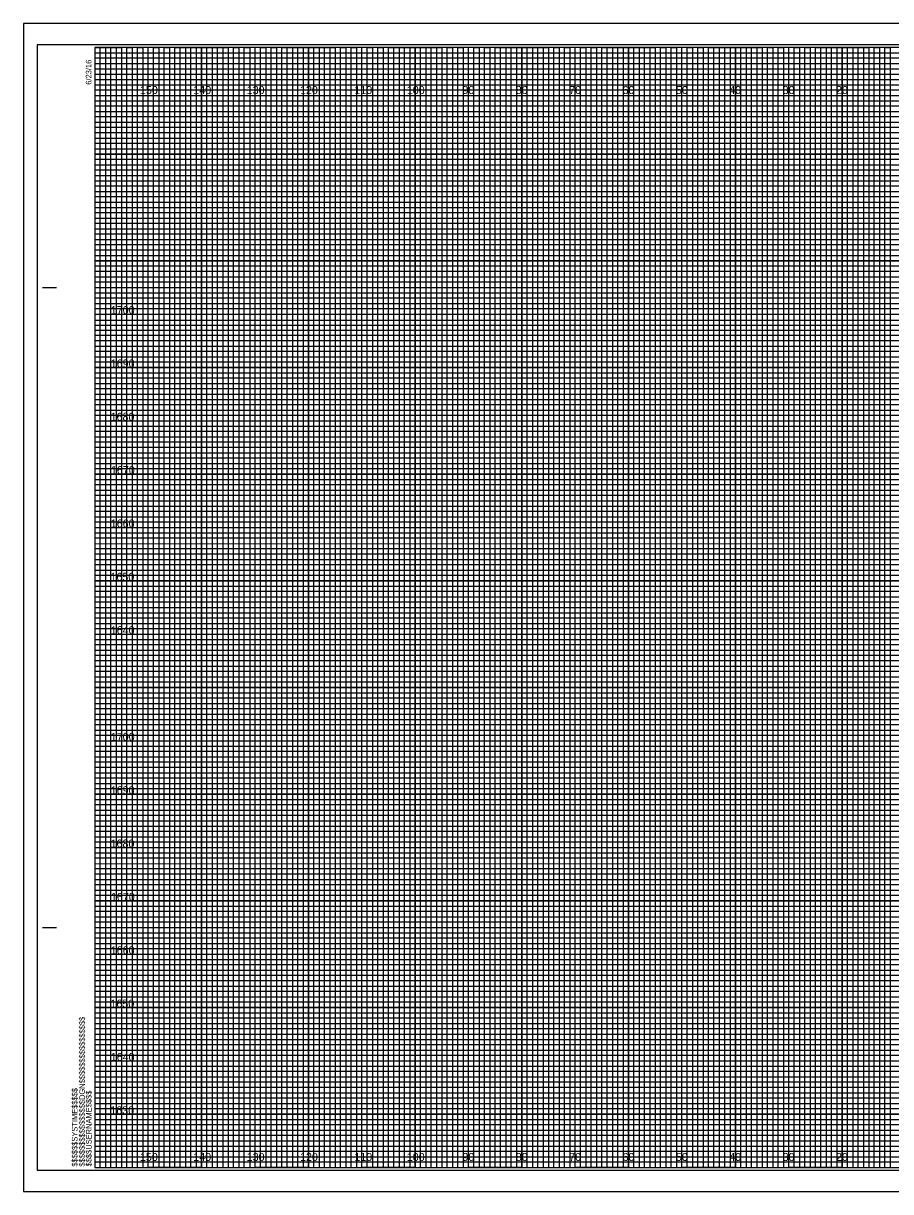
# Model space of a CAD drawing. Extents: x -419 to 4739, y -630 to 13534.
# Drawn here: x 2287.9 to 2450.4, y 635 to 854 of the extents above; entities that cross this region are included whole.
import ezdxf

# ---------------------------------------------------------------- set-up
doc = ezdxf.new("R2010")
doc.units = 0
for name, color, linetype in [('Old_Level_62', 7, 'Continuous'), ('Pattern 1', 7, 'Continuous'), ('Pattern 18', 7, 'Continuous'), ('Pattern 4', 7, 'Continuous'), ('Pattern 5', 7, 'Continuous'), ('Prop Dimension', 7, 'Continuous'), ('Prop Horizontal Alignment', 7, 'Continuous'), ('Raster_Level_0', 7, 'Continuous'), ('Scratch_Level_0', 7, 'Continuous'), ('Scratch_Level_3', 7, 'Continuous'), ('Scratch_Level_5', 7, 'Continuous')]:
    doc.layers.add(name, color=color, linetype=linetype)

msp = doc.modelspace()

# ---------------------------------------------------------------- linework, layer by layer
at = {"layer": 'Old_Level_62'}
for p, q in [((2291.53, 804.53), (2294.03, 804.53)), ((2291.63, 804.53), (2294.13, 804.53)), ((2291.53, 684.53), (2294.03, 684.53)), ((2291.63, 684.53), (2294.13, 684.53)), ((2301.33, 639.53), (2301.33, 639.53)), ((2301.33, 639.53), (2301.33, 639.53)), ((2301.33, 639.53), (2301.33, 639.53)), ((2301.33, 639.53), (2301.33, 639.53)), ((2301.33, 639.53), (2301.33, 639.53)), ((2301.33, 639.53), (2301.33, 639.53)), ((2301.33, 639.53), (2301.33, 639.53))]:
    msp.add_line(p, q, dxfattribs=at)
msp.add_lwpolyline([(2621.33, 849.53), (2301.33, 849.53), (2301.33, 639.53), (2621.33, 639.53)], close=True, dxfattribs=at)
at = {"layer": 'Pattern 18'}
msp.add_lwpolyline([(2287.93, 635.03), (2624.63, 635.03), (2624.63, 854.03), (2287.93, 854.03)], close=True, dxfattribs=at)
at = {"layer": 'Pattern 4'}
for p, q in [((2301.33, 848.53), (2561.33, 848.53)), ((2561.33, 847.51), (2301.33, 847.51)), ((2301.33, 847.51), (2301.33, 846.53)), ((2301.33, 846.53), (2561.33, 846.53)), ((2561.33, 845.42), (2301.33, 845.42)), ((2301.33, 845.42), (2301.33, 843.53)), ((2301.33, 843.53), (2621.33, 843.53))]:
    msp.add_line(p, q, dxfattribs=at)
for points in [[(2301.33, 842.53), (2571.33, 842.53), (2621.33, 842.53), (2621.33, 841.53), (2301.33, 841.53)], [(2301.33, 840.53), (2621.33, 840.53), (2621.33, 838.53), (2301.33, 838.53)], [(2301.33, 837.53), (2621.33, 837.53), (2621.33, 836.53), (2301.33, 836.51)], [(2301.33, 835.53), (2621.33, 835.53), (2621.33, 833.53), (2301.33, 833.53)], [(2301.33, 832.53), (2621.33, 832.53), (2621.33, 831.53), (2301.33, 831.53)], [(2301.33, 830.53), (2621.33, 830.53), (2621.33, 828.53), (2301.33, 828.53)], [(2301.33, 827.53), (2621.33, 827.53), (2621.33, 826.53), (2301.33, 826.53)], [(2301.33, 825.53), (2621.33, 825.53), (2621.33, 823.53), (2301.33, 823.53)], [(2301.33, 822.53), (2621.33, 822.53), (2621.33, 821.53), (2301.33, 821.53)], [(2301.33, 820.53), (2621.33, 820.53), (2621.33, 818.53), (2301.33, 818.53)], [(2301.33, 817.53), (2621.33, 817.53), (2621.33, 816.53), (2301.33, 816.53)], [(2301.33, 815.53), (2621.33, 815.53), (2621.33, 813.48), (2621.33, 812.53), (2621.33, 811.53), (2301.33, 811.53)], [(2301.33, 813.53), (2621.33, 813.53), (2621.33, 812.53), (2301.33, 812.53)], [(2301.33, 810.53), (2621.33, 810.53), (2621.33, 808.53), (2301.33, 808.56)], [(2301.33, 808.56), (2621.33, 808.53), (2621.33, 807.53), (2301.33, 807.53)], [(2301.33, 806.53), (2621.33, 806.53), (2621.33, 805.53), (2301.33, 805.53)], [(2301.33, 803.53), (2621.33, 803.53), (2621.33, 802.53), (2301.33, 802.53)], [(2301.33, 801.53), (2621.33, 801.53), (2621.33, 800.53), (2301.33, 800.53)], [(2301.26, 798.42), (2621.33, 798.42), (2621.33, 797.41), (2301.26, 797.41)], [(2301.33, 796.53), (2621.33, 796.53), (2621.33, 795.53), (2301.33, 795.53)], [(2301.33, 793.53), (2621.33, 793.53), (2621.33, 792.53), (2301.33, 792.53)], [(2301.33, 791.53), (2621.33, 791.53), (2621.33, 790.53), (2301.33, 790.53)], [(2301.33, 788.53), (2621.33, 788.53), (2621.33, 787.53), (2301.33, 787.53)], [(2301.33, 786.53), (2621.33, 786.53), (2621.33, 785.53), (2301.33, 785.53)], [(2301.33, 783.53), (2621.33, 783.53), (2621.33, 782.53), (2301.33, 782.53)], [(2301.33, 781.53), (2621.33, 781.53), (2621.33, 780.53), (2301.33, 780.53)], [(2301.33, 778.53), (2621.33, 778.53), (2621.32, 777.51), (2301.33, 777.53)], [(2301.33, 776.53), (2621.33, 776.53), (2621.33, 775.53), (2301.33, 775.53)], [(2301.33, 773.53), (2621.33, 773.53), (2621.33, 772.53), (2301.33, 772.53)], [(2301.33, 771.53), (2621.33, 771.53), (2621.33, 770.53), (2301.33, 770.53)], [(2301.33, 768.53), (2621.33, 768.53), (2621.33, 767.53), (2301.33, 767.53)], [(2301.33, 766.53), (2621.33, 766.53), (2621.33, 765.53), (2301.33, 765.53)], [(2301.33, 763.53), (2621.33, 763.53), (2621.33, 762.53), (2301.33, 762.53)], [(2301.33, 761.53), (2621.33, 761.53), (2621.33, 760.53), (2301.33, 760.53)], [(2301.33, 758.53), (2621.33, 758.53), (2621.33, 757.53), (2301.33, 757.53)], [(2301.33, 756.52), (2621.4, 756.44), (2621.33, 755.53), (2301.33, 755.53)], [(2301.33, 753.53), (2621.33, 753.53), (2621.33, 752.53), (2301.33, 752.53)], [(2301.33, 751.53), (2621.33, 751.53), (2621.33, 750.53), (2301.33, 750.53)], [(2301.33, 748.53), (2621.33, 748.53), (2621.33, 747.53), (2301.33, 747.53)], [(2301.33, 746.53), (2621.33, 746.53), (2621.33, 745.53), (2301.33, 745.53)], [(2301.33, 743.53), (2621.33, 743.53), (2621.33, 742.53), (2301.33, 742.53)], [(2301.33, 741.53), (2621.33, 741.53), (2621.33, 740.53), (2301.33, 740.53)], [(2301.33, 738.53), (2621.33, 738.53), (2621.33, 737.53), (2301.33, 737.53)], [(2301.33, 736.53), (2621.33, 736.53), (2621.33, 735.53), (2301.33, 735.53)], [(2301.33, 733.53), (2621.33, 733.53), (2621.33, 732.53), (2301.33, 732.53)], [(2301.33, 731.53), (2621.33, 731.53), (2621.33, 730.53), (2301.33, 730.53)], [(2301.33, 728.53), (2621.33, 728.53), (2621.33, 727.53), (2301.33, 727.53)], [(2301.33, 726.53), (2621.33, 726.53), (2621.33, 725.53), (2301.33, 725.53)], [(2301.33, 723.53), (2621.33, 723.53), (2621.33, 722.53), (2301.33, 722.53)], [(2301.33, 721.53), (2621.33, 721.53), (2621.33, 720.53), (2301.33, 720.53)], [(2301.33, 718.53), (2621.33, 718.53), (2621.32, 717.51), (2301.33, 717.53)], [(2301.33, 716.53), (2621.33, 716.53), (2621.33, 715.53), (2301.33, 715.53)], [(2301.33, 713.53), (2621.33, 713.53), (2621.33, 712.53), (2301.33, 712.53)], [(2301.33, 711.53), (2621.33, 711.53), (2621.33, 710.53), (2301.33, 710.53)], [(2301.33, 708.53), (2621.33, 708.53), (2621.33, 707.53), (2301.33, 707.53)], [(2301.33, 706.53), (2621.33, 706.53), (2621.33, 705.53), (2301.33, 705.53)], [(2301.33, 703.53), (2621.33, 703.53), (2621.33, 702.53), (2301.33, 702.53)], [(2301.33, 701.53), (2621.33, 701.53), (2621.33, 700.53), (2301.33, 700.53)], [(2301.33, 698.53), (2621.33, 698.53), (2621.33, 697.53), (2301.33, 697.53)], [(2301.33, 696.52), (2621.4, 696.44), (2621.33, 695.53), (2301.33, 695.53)], [(2301.33, 693.53), (2621.33, 693.53), (2621.33, 692.53), (2301.33, 692.53)], [(2301.33, 691.53), (2621.33, 691.53), (2621.33, 690.53), (2301.33, 690.53)], [(2301.33, 688.53), (2621.33, 688.53), (2621.33, 687.53), (2301.33, 687.53)], [(2301.33, 686.53), (2621.33, 686.53), (2621.33, 685.53), (2301.33, 685.53)], [(2301.33, 683.53), (2621.33, 683.53), (2621.33, 682.53), (2301.33, 682.53)], [(2301.33, 681.53), (2621.33, 681.53), (2621.33, 680.53), (2301.33, 680.53)], [(2301.33, 678.53), (2621.33, 678.53), (2621.33, 677.53), (2301.33, 677.53)], [(2301.33, 676.53), (2621.33, 676.53), (2621.33, 675.53), (2301.33, 675.53)], [(2301.33, 673.53), (2621.33, 673.53), (2621.33, 672.53), (2301.33, 672.53)], [(2301.33, 671.53), (2621.33, 671.53), (2621.33, 670.53), (2301.33, 670.53)], [(2301.33, 668.53), (2621.33, 668.53), (2621.33, 667.53), (2301.33, 667.53)], [(2301.33, 666.53), (2621.33, 666.53), (2621.33, 665.53), (2301.33, 665.53)], [(2301.33, 663.53), (2621.33, 663.53), (2621.33, 662.53), (2301.33, 662.53)], [(2301.33, 661.53), (2621.33, 661.53), (2621.33, 660.53), (2301.33, 660.53)], [(2301.33, 658.53), (2621.33, 658.53), (2621.33, 657.53), (2301.33, 657.53)], [(2301.33, 656.53), (2621.33, 656.53), (2621.33, 655.53), (2301.33, 655.53)], [(2301.33, 653.53), (2621.33, 653.53), (2621.33, 652.53), (2301.33, 652.53)], [(2301.33, 651.53), (2621.33, 651.53), (2621.33, 650.53), (2301.33, 650.53)], [(2301.33, 648.53), (2621.33, 648.53), (2621.33, 647.53), (2301.33, 647.53)], [(2301.33, 646.53), (2621.33, 646.53), (2621.33, 645.53), (2301.33, 645.53)], [(2301.33, 643.53), (2621.33, 643.53), (2621.33, 642.53), (2301.33, 642.53)], [(2301.33, 641.53), (2621.33, 641.53), (2621.33, 640.53), (2301.33, 640.53)]]:
    msp.add_lwpolyline(points, dxfattribs=at)
at = {"layer": 'Pattern 5'}
for p, q in [((2624.63, 854.03), (2287.93, 854.03)), ((2287.93, 854.03), (2287.93, 635.03)), ((2287.93, 635.03), (2624.63, 635.03))]:
    msp.add_line(p, q, dxfattribs=at)
at = {"layer": 'Prop Dimension'}
for points in [[(2301.33, 639.53), (2302.33, 639.53), (2302.33, 849.53), (2303.33, 849.53), (2303.33, 639.53)], [(2303.33, 639.53), (2304.33, 639.53), (2304.33, 849.53), (2305.33, 849.53), (2305.33, 639.53)], [(2306.33, 639.53), (2307.33, 639.53), (2307.33, 849.53), (2308.33, 849.53), (2308.33, 639.53)], [(2308.33, 639.53), (2309.33, 639.53), (2309.33, 849.53), (2310.33, 849.53), (2310.33, 639.53)], [(2311.33, 639.53), (2312.33, 639.53), (2312.33, 849.53), (2313.33, 849.53), (2313.33, 639.53)], [(2313.33, 639.53), (2314.33, 639.53), (2314.33, 849.53), (2315.33, 849.53), (2315.33, 639.53)], [(2316.33, 639.53), (2317.33, 639.53), (2317.33, 849.53), (2318.33, 849.53), (2318.33, 639.53)], [(2318.33, 639.53), (2319.33, 639.53), (2319.33, 849.53), (2320.33, 849.53), (2320.33, 639.53)], [(2321.33, 639.53), (2322.33, 639.53), (2322.33, 849.53), (2323.33, 849.53), (2323.33, 639.53)], [(2323.33, 639.53), (2324.33, 639.53), (2324.33, 849.53), (2325.33, 849.53), (2325.33, 639.53)], [(2326.33, 639.53), (2327.33, 639.53), (2327.33, 849.53), (2328.33, 849.53), (2328.33, 639.53)], [(2328.33, 639.53), (2329.33, 639.53), (2329.33, 849.53), (2330.33, 849.53), (2330.33, 639.53)], [(2331.33, 639.53), (2332.33, 639.53), (2332.33, 849.53), (2333.33, 849.53), (2333.33, 639.53)], [(2333.33, 639.53), (2334.33, 639.53), (2334.33, 849.53), (2335.33, 849.53), (2335.33, 639.53)], [(2336.33, 639.53), (2337.33, 639.53), (2337.33, 849.53), (2338.33, 849.53), (2338.33, 639.53)], [(2338.33, 639.53), (2339.33, 639.53), (2339.33, 849.53), (2340.33, 849.53), (2340.33, 639.53)], [(2341.33, 639.53), (2342.33, 639.53), (2342.33, 849.53), (2343.33, 849.53), (2343.33, 639.53)], [(2343.33, 639.53), (2344.33, 639.53), (2344.33, 849.53), (2345.33, 849.53), (2345.33, 639.53)], [(2346.33, 639.53), (2347.33, 639.53), (2347.33, 849.53), (2348.33, 849.53), (2348.33, 639.53)], [(2348.33, 639.53), (2349.33, 639.53), (2349.33, 849.53), (2350.33, 849.53), (2350.33, 639.53)], [(2351.33, 639.53), (2352.33, 639.53), (2352.33, 849.53), (2353.33, 849.53), (2353.33, 639.53)], [(2353.33, 639.53), (2354.33, 639.53), (2354.33, 849.53), (2355.33, 849.53), (2355.33, 639.53)], [(2356.33, 639.53), (2357.33, 639.53), (2357.33, 849.53), (2358.33, 849.53), (2358.33, 639.53)], [(2358.33, 639.53), (2359.33, 639.53), (2359.33, 849.53), (2360.33, 849.53), (2360.33, 639.53)], [(2361.33, 639.53), (2362.33, 639.53), (2362.33, 849.53), (2363.33, 849.53), (2363.33, 639.53)], [(2363.33, 639.53), (2364.33, 639.53), (2364.33, 849.53), (2365.33, 849.53), (2365.33, 639.53)], [(2366.33, 639.53), (2367.33, 639.53), (2367.33, 849.53), (2368.33, 849.53), (2368.33, 639.53)], [(2368.33, 639.53), (2369.33, 639.53), (2369.33, 849.53), (2370.33, 849.53), (2370.33, 639.53)], [(2371.33, 639.53), (2372.33, 639.53), (2372.33, 849.53), (2373.33, 849.53), (2373.33, 639.53)], [(2373.33, 639.53), (2374.33, 639.53), (2374.33, 849.53), (2375.33, 849.53), (2375.33, 639.53)], [(2376.33, 639.53), (2377.33, 639.53), (2377.33, 849.53), (2378.33, 849.53), (2378.33, 639.53)], [(2378.33, 639.53), (2379.33, 639.53), (2379.33, 849.53), (2380.33, 849.53), (2380.33, 639.53)], [(2381.33, 639.53), (2382.33, 639.53), (2382.33, 849.53), (2383.33, 849.53), (2383.33, 639.53)], [(2383.33, 639.53), (2384.33, 639.53), (2384.33, 849.53), (2385.33, 849.53), (2385.33, 639.53)], [(2386.33, 639.53), (2387.33, 639.53), (2387.33, 849.53), (2388.33, 849.53), (2388.33, 639.53)], [(2388.33, 639.53), (2389.33, 639.53), (2389.33, 849.53), (2390.33, 849.53), (2390.33, 639.53)], [(2391.33, 639.53), (2392.33, 639.53), (2392.33, 849.53), (2393.33, 849.53), (2393.33, 639.53)], [(2393.33, 639.53), (2394.33, 639.53), (2394.33, 849.53), (2395.33, 849.53), (2395.33, 639.53)], [(2396.33, 639.53), (2397.33, 639.53), (2397.33, 849.53), (2398.33, 849.53), (2398.33, 639.53)], [(2398.33, 639.53), (2399.33, 639.53), (2399.33, 849.53), (2400.33, 849.53), (2400.33, 639.53)], [(2401.33, 639.53), (2402.33, 639.53), (2402.33, 849.53), (2403.33, 849.53), (2403.33, 639.53)], [(2403.33, 639.53), (2404.33, 639.53), (2404.33, 849.53), (2405.33, 849.53), (2405.33, 639.53)], [(2406.33, 639.53), (2407.33, 639.53), (2407.33, 849.53), (2408.33, 849.53), (2408.33, 639.53)], [(2408.33, 639.53), (2409.33, 639.53), (2409.33, 849.53), (2410.33, 849.53), (2410.33, 639.53)], [(2411.33, 639.53), (2412.33, 639.53), (2412.33, 849.53), (2413.33, 849.53), (2413.33, 639.53)], [(2413.33, 639.53), (2414.33, 639.53), (2414.33, 849.53), (2415.33, 849.53), (2415.33, 639.53)], [(2416.33, 639.53), (2417.33, 639.53), (2417.33, 849.53), (2418.33, 849.53), (2418.33, 639.53)], [(2418.33, 639.53), (2419.33, 639.53), (2419.33, 849.53), (2420.33, 849.53), (2420.33, 639.53)], [(2421.33, 639.53), (2422.33, 639.53), (2422.33, 849.53), (2423.33, 849.53), (2423.33, 639.53)], [(2423.33, 639.53), (2424.33, 639.53), (2424.33, 849.53), (2425.33, 849.53), (2425.33, 639.53)], [(2426.33, 639.53), (2427.33, 639.53), (2427.33, 849.53), (2428.33, 849.53), (2428.33, 639.53)], [(2428.33, 639.53), (2429.33, 639.53), (2429.33, 849.53), (2430.33, 849.53), (2430.33, 639.53)], [(2431.33, 639.53), (2432.33, 639.53), (2432.33, 849.53), (2433.33, 849.53), (2433.33, 639.53)], [(2433.33, 639.53), (2434.33, 639.53), (2434.33, 849.53), (2435.33, 849.53), (2435.33, 639.53)], [(2436.33, 639.53), (2437.33, 639.53), (2437.33, 849.53), (2438.33, 849.53), (2438.33, 639.53)], [(2438.33, 639.53), (2439.33, 639.53), (2439.33, 849.53), (2440.33, 849.53), (2440.33, 639.53)], [(2441.33, 639.53), (2442.33, 639.53), (2442.33, 849.53), (2443.33, 849.53), (2443.33, 639.53)], [(2443.33, 639.53), (2444.33, 639.53), (2444.33, 849.53), (2445.33, 849.53), (2445.33, 639.53)], [(2446.33, 639.53), (2447.33, 639.53), (2447.33, 849.53), (2448.33, 849.53), (2448.33, 639.53)], [(2448.33, 639.53), (2449.33, 639.53), (2449.33, 849.53), (2450.33, 849.53), (2450.33, 639.53)]]:
    msp.add_lwpolyline(points, dxfattribs=at)
at = {"layer": 'Prop Horizontal Alignment'}
for points in [[(2301.33, 849.53), (2306.33, 849.53), (2306.33, 639.53), (2316.33, 639.53), (2316.33, 849.53), (2326.33, 849.53), (2326.33, 639.53), (2336.33, 639.53), (2336.33, 849.53), (2346.33, 849.53), (2346.33, 639.53), (2356.33, 639.53), (2356.33, 849.53), (2366.33, 849.53), (2366.33, 639.53), (2376.33, 639.53), (2376.33, 849.53), (2386.33, 849.53), (2386.33, 639.53), (2396.33, 639.53), (2396.33, 849.53), (2406.33, 849.53), (2406.33, 639.53), (2416.33, 639.53), (2416.33, 849.53), (2426.33, 849.53), (2426.33, 639.53), (2436.33, 639.53), (2436.33, 849.53), (2446.33, 849.53), (2446.33, 639.53), (2456.33, 639.53)], [(2301.33, 844.53), (2576.33, 844.53)], [(2301.33, 824.53), (2621.33, 824.53), (2621.33, 834.53), (2301.33, 834.53)], [(2301.33, 804.53), (2621.33, 804.53), (2621.33, 814.53), (2301.33, 814.53)], [(2301.33, 784.53), (2621.33, 784.53), (2621.33, 794.53), (2301.33, 794.53)], [(2301.33, 764.53), (2621.33, 764.53), (2621.33, 774.53), (2301.33, 774.53)], [(2301.33, 744.53), (2621.33, 744.53), (2621.33, 754.53), (2301.33, 754.53)], [(2301.33, 724.53), (2621.33, 724.53), (2621.33, 734.53), (2301.33, 734.53)], [(2301.33, 704.53), (2621.33, 704.53), (2621.33, 714.53), (2301.33, 714.53)], [(2301.33, 684.53), (2621.33, 684.53), (2621.33, 694.53), (2301.33, 694.53)], [(2301.33, 664.53), (2621.33, 664.53), (2621.33, 674.53), (2301.33, 674.53)], [(2301.33, 644.53), (2621.33, 644.53), (2621.33, 654.53), (2301.33, 654.53)]]:
    msp.add_lwpolyline(points, dxfattribs=at)
at = {"layer": 'Scratch_Level_0'}
for p, q in [((2311.33, 639.53), (2311.33, 849.53)), ((2321.33, 639.53), (2321.33, 849.53)), ((2331.33, 639.53), (2331.33, 849.53)), ((2341.33, 639.53), (2341.33, 849.53)), ((2351.33, 639.53), (2351.33, 849.53)), ((2361.33, 639.53), (2361.33, 849.53)), ((2371.33, 639.53), (2371.33, 849.53)), ((2381.33, 639.53), (2381.33, 849.53)), ((2391.33, 639.53), (2391.33, 849.53)), ((2401.33, 639.53), (2401.33, 849.53)), ((2411.33, 639.53), (2411.33, 849.53)), ((2421.33, 639.53), (2421.33, 849.53)), ((2431.33, 639.53), (2431.33, 849.53)), ((2441.33, 639.53), (2441.33, 849.53)), ((2301.33, 839.53), (2621.33, 839.53)), ((2301.33, 829.53), (2621.33, 829.53)), ((2301.33, 819.53), (2621.33, 819.53)), ((2301.33, 809.53), (2621.33, 809.53)), ((2301.33, 799.53), (2621.33, 799.53)), ((2301.33, 789.53), (2621.33, 789.53)), ((2301.33, 779.53), (2621.33, 779.53)), ((2301.33, 769.53), (2621.33, 769.53)), ((2301.33, 759.53), (2621.33, 759.53)), ((2301.33, 749.53), (2621.33, 749.53)), ((2301.33, 739.53), (2621.33, 739.53)), ((2301.33, 729.53), (2621.33, 729.53)), ((2301.33, 719.53), (2621.33, 719.53)), ((2301.33, 709.53), (2621.33, 709.53)), ((2301.33, 699.53), (2621.33, 699.53)), ((2301.33, 689.53), (2621.33, 689.53)), ((2301.33, 679.53), (2621.33, 679.53)), ((2301.33, 669.53), (2621.33, 669.53)), ((2301.33, 659.53), (2621.33, 659.53)), ((2301.33, 649.53), (2621.33, 649.53))]:
    msp.add_line(p, q, dxfattribs=at)
at = {"layer": 'Scratch_Level_3'}
for p, q in [((2311.33, 849.53), (2301.33, 849.53)), ((2311.33, 639.53), (2311.33, 849.53)), ((2331.33, 849.53), (2321.33, 849.53)), ((2321.33, 849.53), (2321.33, 639.53)), ((2331.33, 639.53), (2331.33, 849.53)), ((2351.33, 849.53), (2341.33, 849.53)), ((2341.33, 849.53), (2341.33, 639.53)), ((2351.33, 639.53), (2351.33, 849.53)), ((2371.33, 849.53), (2361.33, 849.53)), ((2361.33, 849.53), (2361.33, 639.53)), ((2371.33, 639.53), (2371.33, 849.53)), ((2391.33, 849.53), (2381.33, 849.53)), ((2381.33, 849.53), (2381.33, 639.53)), ((2391.33, 639.53), (2391.33, 849.53)), ((2411.33, 849.53), (2401.33, 849.53)), ((2401.33, 849.53), (2401.33, 639.53)), ((2411.33, 639.53), (2411.33, 849.53)), ((2431.33, 849.53), (2421.33, 849.53)), ((2421.33, 849.53), (2421.33, 639.53)), ((2431.33, 639.53), (2431.33, 849.53)), ((2451.33, 849.53), (2441.33, 849.53)), ((2441.33, 849.53), (2441.33, 639.53)), ((2321.33, 639.53), (2311.33, 639.53)), ((2341.33, 639.53), (2331.33, 639.53)), ((2361.33, 639.53), (2351.33, 639.53)), ((2381.33, 639.53), (2371.33, 639.53)), ((2401.33, 639.53), (2391.33, 639.53)), ((2421.33, 639.53), (2411.33, 639.53)), ((2441.33, 639.53), (2431.33, 639.53))]:
    msp.add_line(p, q, dxfattribs=at)
for points in [[(2301.33, 839.53), (2621.33, 839.53), (2621.33, 829.53), (2301.33, 829.53)], [(2301.33, 819.53), (2621.33, 819.53), (2621.33, 809.53), (2301.33, 809.53)], [(2301.33, 799.53), (2621.33, 799.53), (2621.33, 789.53), (2301.33, 789.53)], [(2301.33, 779.53), (2621.33, 779.53), (2621.33, 769.53), (2301.33, 769.53)], [(2301.33, 759.53), (2621.33, 759.53), (2621.33, 749.53), (2301.33, 749.53)], [(2301.33, 739.53), (2621.33, 739.53), (2621.33, 729.53), (2301.33, 729.53)], [(2301.33, 719.53), (2621.33, 719.53), (2621.33, 709.53), (2301.33, 709.53)], [(2301.33, 699.53), (2621.33, 699.53), (2621.33, 689.53), (2301.33, 689.53)], [(2301.33, 679.53), (2621.33, 679.53), (2621.33, 669.53), (2301.33, 669.53)], [(2301.33, 659.53), (2621.33, 659.53), (2621.33, 649.53), (2301.33, 649.53)]]:
    msp.add_lwpolyline(points, dxfattribs=at)
at = {"layer": 'Scratch_Level_5'}
msp.add_lwpolyline([(2290.53, 639.03), (2623.73, 639.03), (2623.73, 850.03), (2290.53, 850.03)], close=True, dxfattribs=at)

# ---------------------------------------------------------------- texts
at = {"layer": 'Old_Level_62'}
for s, p in [('6/23/16', (2300.68, 842.53)), ('$$$$$$$$$$$$$$$$DGN$$$$$$$$$$$$$$$$', (2299.45, 639.71)), ('$$$$$$SYSTIME$$$$$', (2298.07, 639.71)), ('$$$$USERNAME$$$$', (2300.71, 639.76))]:
    msp.add_text(s, height=1.05, rotation=90, dxfattribs=at).set_placement(p)
at = {"layer": 'Pattern 1'}
for s, p in [('1700', (2304.31, 799.53)), ('1690', (2304.3, 789.53)), ('1680', (2304.27, 779.53)), ('1670', (2304.33, 769.53)), ('1660', (2304.3, 759.53)), ('1650', (2304.25, 749.53)), ('1640', (2304.3, 739.53)), ('1700', (2304.31, 719.53)), ('1690', (2304.3, 709.53)), ('1680', (2304.27, 699.53)), ('1670', (2304.33, 689.53)), ('1660', (2304.3, 679.53)), ('1650', (2304.25, 669.53)), ('1640', (2304.3, 659.53)), ('1630', (2304.22, 649.53))]:
    msp.add_text(s, height=1.5, dxfattribs=at).set_placement(p)
at = {"layer": 'Raster_Level_0'}
for s, p in [('150', (2309.77, 840.78)), ('140', (2319.77, 840.78)), ('130', (2329.77, 840.78)), ('120', (2339.77, 840.78)), ('110', (2349.95, 840.78)), ('100', (2359.77, 840.78)), ('90', (2370.19, 840.78)), ('80', (2380.19, 840.78)), ('70', (2390.19, 840.78)), ('60', (2400.19, 840.78)), ('50', (2410.19, 840.78)), ('40', (2420.19, 840.78)), ('30', (2430.19, 840.78)), ('20', (2440.19, 840.78)), ('150', (2309.77, 640.78)), ('140', (2319.77, 640.78)), ('130', (2329.77, 640.78)), ('120', (2339.77, 640.78)), ('110', (2349.95, 640.78)), ('100', (2359.77, 640.78)), ('90', (2370.19, 640.78)), ('80', (2380.19, 640.78)), ('70', (2390.19, 640.78)), ('60', (2400.19, 640.78)), ('50', (2410.19, 640.78)), ('40', (2420.19, 640.78)), ('30', (2430.19, 640.78)), ('20', (2440.19, 640.78))]:
    msp.add_text(s, height=1.5, dxfattribs=at).set_placement(p)

doc.saveas('drawing.dxf')
